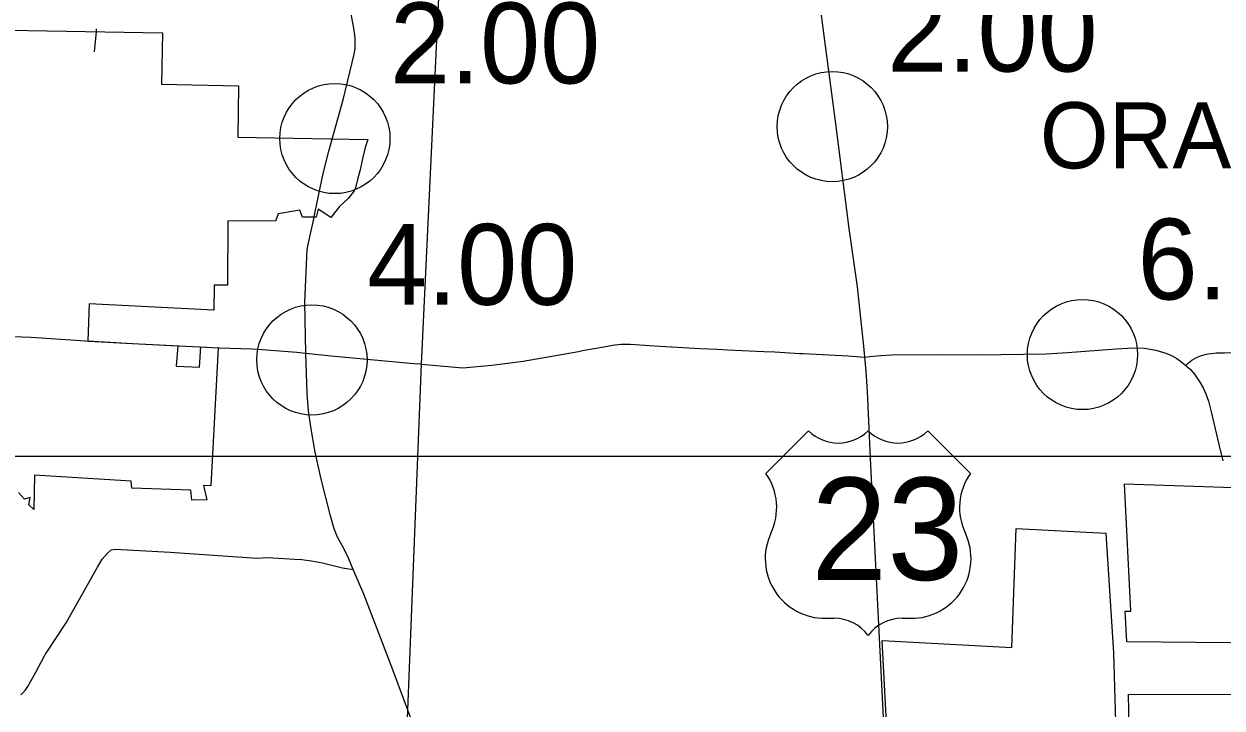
# Model space of a CAD drawing. Extents: x 1659811 to 1934326, y 644115 to 934867.
# Drawn here: x 1812113 to 1828424, y 781248 to 790558 of the extents above; entities that cross this region are included whole.
import ezdxf

# ---------------------------------------------------------------- set-up
doc = ezdxf.new("R2010")
doc.units = 0
for name, color, linetype in [('Default', 7, 'Continuous'), ('GM_X_City_Street', 7, 'Continuous'), ('GM_X_Corporation', 7, 'Continuous'), ('GM_X_County_Road', 7, 'Continuous'), ('GM_X_State_Route', 7, 'Continuous'), ('GM_X_Township', 7, 'Continuous'), ('GM_X_Township_Road', 7, 'Continuous'), ('GM_X_Township_Text', 7, 'Continuous'), ('GM_X_US_Route', 7, 'Continuous'), ('GM_X_US_Shield', 7, 'Continuous'), ('SC_Scratch1', 7, 'Continuous')]:
    doc.layers.add(name, color=color, linetype=linetype)

msp = doc.modelspace()

# ---------------------------------------------------------------- linework, layer by layer
at = {"layer": 'Default'}
for centre in [(1823118, 789161), (1816346, 788999), (1816034, 785986), (1826524, 786059)]:
    msp.add_circle(centre, 750, dxfattribs=at)
at = {"layer": 'GM_X_City_Street'}
msp.add_lwpolyline([(1813075, 790181), (1813101, 790456), (1813101, 790491)], dxfattribs=at)
at = {"layer": 'GM_X_Corporation'}
for points in [[(1810855, 790494), (1814000, 790437), (1813987, 789737), (1815036, 789718), (1815023, 789018), (1816797, 788985), (1816759, 788876), (1816729, 788747), (1816691, 788572), (1816660, 788458), (1816629, 788327), (1816608, 788285), (1816530, 788186), (1816408, 788075), (1816292, 787922), (1816117, 788037), (1816092, 787927), (1815906, 787930), (1815870, 788024), (1815574, 787972), (1815539, 787875), (1814889, 787878), (1814886, 787002), (1814701, 787002), (1814699, 786665), (1813003, 786749), (1812982, 786246), (1813591, 786209), (1814206, 786179), (1814187, 785899), (1814503, 785888), (1814522, 786163), (1814757, 786152), (1814657, 784274), (1814557, 784275), (1814602, 784081), (1814401, 784079), (1814383, 784214), (1813584, 784242), (1813574, 784337), (1812256, 784419), (1812247, 783951), (1812181, 784013), (1812199, 784114), (1812120, 784091), (1812040, 784183)], [(1829006, 782129), (1827128, 782148), (1827107, 782565), (1827182, 782566), (1827094, 784298), (1829525, 784216)], [(1823897, 780274), (1823795, 782165), (1825564, 782072), (1825620, 783690), (1826843, 783626), (1826946, 782000), (1827027, 779186)], [(1827198, 779170), (1827151, 781435), (1828757, 781433)]]:
    msp.add_lwpolyline(points, dxfattribs=at)
at = {"layer": 'GM_X_County_Road'}
msp.add_lwpolyline([(1827933, 785912), (1827967, 785947), (1828014, 785981), (1828077, 786017), (1828143, 786045), (1828212, 786066), (1828234, 786070), (1828276, 786074), (1828349, 786080), (1828458, 786082), (1829120, 786088), (1829721, 786095), (1830137, 786102)], dxfattribs=at)
at = {"layer": 'GM_X_State_Route'}
for points in [[(1816266, 788827), (1816308, 788989), (1816463, 789546), (1816611, 790147), (1816623, 790230), (1816624, 790350), (1816620, 790409), (1816599, 790530), (1816533, 790876), (1816487, 791123), (1816430, 791427), (1816402, 791554), (1816384, 791615), (1816350, 791700), (1816268, 791852), (1816208, 791960), (1816169, 792032), (1816020, 792294), (1815964, 792391), (1815825, 792638), (1815801, 792684), (1815789, 792708)], [(1816069, 787957), (1816079, 787999), (1816187, 788523), (1816266, 788827)], [(1816013, 787700), (1816053, 787885), (1816069, 787957)], [(1815949, 786077), (1815949, 786077), (1815938, 786769), (1815968, 787495), (1816013, 787700)], [(1804441, 786683), (1805006, 786649), (1806106, 786604), (1806408, 786590), (1806429, 786589), (1806951, 786560), (1807360, 786549), (1807446, 786547), (1807709, 786531), (1808840, 786478), (1810274, 786407), (1811167, 786357), (1811832, 786309), (1812210, 786294), (1812953, 786246)], [(1812953, 786246), (1812990, 786243), (1813591, 786209), (1814771, 786150), (1814772, 786150)], [(1815949, 786077), (1816340, 786036), (1817421, 785936), (1817504, 785931), (1817524, 785929), (1818089, 785876), (1818484, 785913), (1818908, 785967), (1819089, 785999), (1819665, 786100), (1819718, 786112), (1820036, 786168), (1820128, 786185), (1820241, 786200), (1820367, 786198), (1820698, 786179), (1821320, 786143), (1821549, 786130)], [(1814772, 786150), (1815220, 786136), (1815357, 786129), (1815594, 786109), (1815826, 786090), (1815949, 786077)], [(1818019, 779405), (1817795, 780002), (1817338, 781221), (1817148, 781730), (1816994, 782133), (1816739, 782797), (1816596, 783133), (1816530, 783286), (1816466, 783417), (1816381, 783573), (1816336, 783687), (1816285, 783865), (1816160, 784364), (1816076, 784730), (1816020, 785073), (1815987, 785293), (1815970, 785528), (1815949, 786077)], [(1821549, 786130), (1821693, 786122), (1822187, 786100), (1822334, 786095)], [(1822334, 786095), (1822671, 786075), (1822720, 786071), (1823334, 786043), (1823500, 786028), (1823563, 786025)], [(1823563, 786025), (1823628, 786033), (1823775, 786046), (1823922, 786053), (1824581, 786061), (1825105, 786055), (1826030, 786067), (1826319, 786087), (1826985, 786136), (1827143, 786145), (1827249, 786149), (1827367, 786145), (1827524, 786120), (1827661, 786077), (1827737, 786044), (1827810, 786003), (1827879, 785955), (1827933, 785912), (1827993, 785854), (1828049, 785790), (1828123, 785685), (1828168, 785604), (1828202, 785526), (1828238, 785425), (1828282, 785261), (1828387, 784818), (1828437, 784614)]]:
    msp.add_lwpolyline(points, dxfattribs=at)
at = {"layer": 'GM_X_Township'}
msp.add_lwpolyline([(1817250, 778977), (1817281, 779754), (1817338, 781221), (1817524, 785929), (1817856, 792932), (1818194, 800042), (1818544, 806864)], dxfattribs=at)
at = {"layer": 'GM_X_Township_Road'}
msp.add_lwpolyline([(1812070, 781428), (1812129, 781487), (1812166, 781542), (1812275, 781737), (1812394, 781957), (1812402, 781975), (1812415, 781994), (1812688, 782408), (1813116, 783166), (1813176, 783276), (1813250, 783357), (1813300, 783402), (1813355, 783411), (1814105, 783369), (1815284, 783286), (1815431, 783297), (1815798, 783276), (1815898, 783270), (1816026, 783253), (1816177, 783222), (1816452, 783156), (1816596, 783133)], dxfattribs=at)
at = {"layer": 'GM_X_US_Route'}
for points in [[(1823552, 786128), (1823460, 786981), (1823349, 787775), (1823161, 789237), (1823026, 790261), (1822930, 790991), (1822896, 791248), (1822775, 792154), (1822731, 792433), (1822700, 792611), (1822684, 792674), (1822657, 792813), (1822450, 793722), (1822328, 794267), (1822235, 794713), (1822226, 794758), (1822121, 795276), (1821937, 796186), (1821679, 797401), (1821619, 797688), (1821461, 798452)], [(1823558, 786077), (1823552, 786128)], [(1823563, 786025), (1823558, 786077)], [(1823936, 778682), (1823645, 784547), (1823597, 785555), (1823580, 785831), (1823563, 786025)]]:
    msp.add_lwpolyline(points, dxfattribs=at)
at = {"layer": 'GM_X_US_Shield'}
for p, q in [((1822794, 785021), (1822214, 784441)), ((1822794, 785021), (1822214, 784441)), ((1824998, 784441), (1824418, 785021)), ((1824998, 784441), (1824418, 785021)), ((1823026, 782469), (1823142, 782469)), ((1823026, 782469), (1823142, 782469)), ((1824070, 782469), (1824186, 782469)), ((1824070, 782469), (1824186, 782469))]:
    msp.add_line(p, q, dxfattribs=at)
for centre, radius, start, end in [((1823200, 785435), 580, 225.573, 314.427), ((1823200, 785435), 580, 225.573, 314.427), ((1824012, 785435), 580, 225.573, 314.427), ((1824012, 785435), 580, 225.573, 314.427), ((1821549, 783975), 812, 334.5471, 35.0009), ((1821549, 783975), 812, 334.5471, 35.0009), ((1825663, 783975), 812, 144.9991, 205.4529), ((1825663, 783975), 812, 144.9991, 205.4529), ((1823017, 783281), 812, 154.8319, 270.6383), ((1823017, 783281), 812, 154.8319, 270.6383), ((1824195, 783281), 812, 269.3617, 25.1681), ((1824195, 783281), 812, 269.3617, 25.1681), ((1823142, 781889), 580, 36.8699, 90), ((1823142, 781889), 580, 36.8699, 90), ((1824070, 781889), 580, 90, 143.1301), ((1824070, 781889), 580, 90, 143.1301)]:
    msp.add_arc(centre, radius, start, end, dxfattribs=at)
at = {"layer": 'SC_Scratch1'}
msp.add_lwpolyline([(1730291, 784675), (1926541, 784675), (1926541, 650175), (1730291, 650175)], close=True, dxfattribs=at)

# ---------------------------------------------------------------- texts
at = {"layer": 'Default'}
for s, p in [('2.00', (1823868, 789911)), ('2.00', (1817096, 789749)), ('4.00', (1816784, 786736)), ('6.00', (1827274, 786809))]:
    msp.add_text(s, height=1100, dxfattribs=at).set_placement(p)
at = {"layer": 'GM_X_Township_Text'}
msp.add_text('ORANGE', height=900, rotation=0, dxfattribs=at).set_placement((1825944, 788593))
at = {"layer": 'GM_X_US_Shield'}
msp.add_text('23', height=1392.2, dxfattribs=at).set_placement((1822831, 782991))
msp.add_text('23', height=1392.2, dxfattribs=at).set_placement((1822831, 782991))

doc.saveas('drawing.dxf')
